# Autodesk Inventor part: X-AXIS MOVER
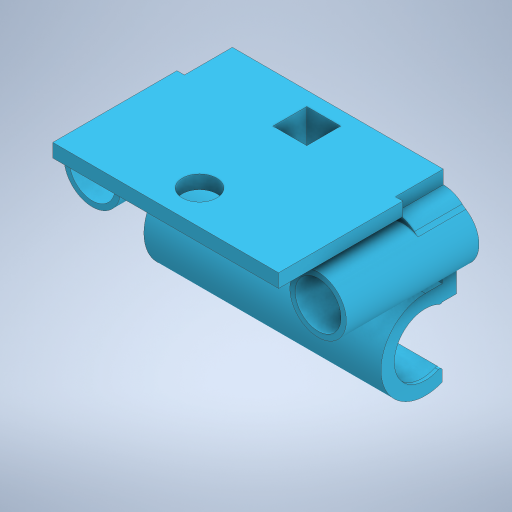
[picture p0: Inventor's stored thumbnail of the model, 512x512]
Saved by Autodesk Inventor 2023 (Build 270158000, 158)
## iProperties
Created: 2025-07
Part Number: X-AXIS MOVER
Material: Generic
Document SubType Name: Modeling
Designer: erjon
Density: 1 g/cm^3
Appearance: Default
Author: erjon
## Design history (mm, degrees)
feature "Base1"
sketch "Sketch1"
  geometry: L1 (-7, 2)-(-7, -1.767); L2 (-10, 9)-(0, 9); L3 (0, 0)-(0, 10.101) reference; L4 (-10, 9)-(0, 9); L5 (0, 10.101)-(-10, 10.101) reference; L6 (-10, 9.148)-(-10, 10.101) reference; L7 (-4, 9.148)-(-10, 9.148) reference; L8 (-4, 9)-(-4, 9.148) reference; L9 (-10, 9)-(-4, 9) reference; L10 (-10, 8)-(-10, 9) reference; L11 (-9.399, 7.335)-(-9.5, 7.5) reference; L12 (-9.308, -3.538)-(-9.241, -3.404) reference; L13 (-5, -5)-(-9, -5) reference; L14 (0, 10.101)-(0, 0) reference; L15 (-4.601, 7.335)-(-4.5, 7.5); L16 (-4, 8)-(-4, 9); L17 (-4.692, -3.538)-(-4.759, -3.404); L18 (-9, -5)-(-5, -5); L19 (-14, 0)-(-14, 10.101); L20 (-14, 10.101)-(-14, 0); L21 (-4, 9)-(-14, 9); L22 (-4, 9)-(-4, 9.148) reference; L23 (-4, 9)-(-14, 9); A1 r 5.85 centre (-7, 2) between (-9.241, -3.404) and (-9.399, 7.335) reference; A2 r 0.5 centre (-9.5, 8) between (-10, 8) and (-9.5, 7.5) reference; A3 r 5.85 centre (-7, 2) between (-9.241, -3.404) and (-9.399, 7.335) reference; A4 r 0.5 centre (-9.5, -4) between (-9.308, -3.538) and (-10, -4) reference; A5 r 1 centre (-9, -4) between (-10, -4) and (-9, -5) reference; A6 r 5 centre (-5, 0) between (-5, -5) and (0, 0) reference; A7 r 5.85 centre (-7, 2) between (-4.601, 7.335) and (-4.759, -3.404); A8 r 0.5 centre (-4.5, 8) between (-4.5, 7.5) and (-4, 8); A9 r 5.85 centre (-7, 2) between (-4.601, 7.335) and (-4.759, -3.404); A10 r 0.5 centre (-4.5, -4) between (-4, -4) and (-4.692, -3.538); A11 r 1 centre (-5, -4) between (-5, -5) and (-4, -4); A12 r 5 centre (-9, 0) between (-14, 0) and (-9, -5); 12 further points
  constraints: 22 end point, 21 symmetric about line, 12 point on circle, 6 centre point, 2 collinear, 2 point on line, 1 horizontal, 1 vertical, 6 other
  node "Projected Loop1"
extrude "Extrusion1" join sketch "Sketch1" stored distance "d0" = 10; taper "d1" = 0 deg
sketch "Sketch2"
  geometry: 1 further point
extrude "Extrusion2" cut sketch "Sketch1" distance "d2" = 100; taper "d3" = 0 deg
sketch "Sketch3"
  geometry: L1 (9.399, 7.335)-(14, 7.335); L2 (14, 7.335)-(14, 9); L3 (14, 9)-(10, 9); L4 (9.399, 7.335)-(9.5, 7.5) reference; L5 (10, 8)-(10, 9) reference; A1 r 0.5 centre (9.5, 8) between (9.5, 7.5) and (10, 8) reference; 1 further point
  constraints: 6 end point, 2 perpendicular, 1 horizontal
extrude "Extrusion3" join sketch "Sketch3" stored distance "d4" = 100; taper "d5" = 0 deg
sketch "Sketch4"
  geometry: L1 (39.682, -15.065)-(39.682, -12.299) reference; L2 (37.364, -1.4)-(37.364, 0) reference; L3 (0, 0)-(37.364, 0) reference; L4 (0, -1.4)-(0, 0) reference; L5 (-2.318, -12.299)-(-2.318, -15.065) reference; L6 (-2.318, -15.065)-(39.682, -15.065) reference; A1 r 5 centre (38.682, -7.4) between (39.682, -12.299) and (41.364, -3.18) reference; A2 r 5 centre (44.047, 1.039) between (40.705, -2.68) and (41.364, -3.18) reference; A3 r 5 centre (37.364, -6.4) between (40.705, -2.68) and (37.364, -1.4) reference; A4 r 5 centre (0, -6.4) between (0, -1.4) and (-3.341, -2.68) reference; A5 r 5 centre (-6.683, 1.039) between (-4, -3.18) and (-3.341, -2.68) reference; A6 r 5 centre (-1.318, -7.4) between (-4, -3.18) and (-2.318, -12.299) reference; 1 further point
extrude "Extrusion4" cut sketch "Sketch4" distance "d6" = 1.5; taper "d7" = 0 deg
sketch "Sketch5"
  geometry: L1 (33.682, -6)-(3.682, -6); L2 (18.682, -6)-(18.682, -12); L3 (39.682, -12)-(-2.318, -12) reference; L4 (18.682, -12)-(15.682, -12); L5 (15.682, -12)-(21.682, -12); L6 (21.682, -12)-(21.682, 0); L7 (37.364, 0)-(0, 0) reference; L8 (21.682, 0)-(15.682, 0); L9 (15.682, 0)-(15.682, -12); A1 r 5 centre (-1.318, -6) between (-2.318, -10.899) and (-4, -1.78) reference; 5 further points
  constraints: 14 end point, 3 perpendicular, 2 midpoint, 2 point on line, 1 horizontal, 1 horizontal alignment, 1 point on circle, 1 other
  dimensions: "d8" = 3 distance of L2.end L4.end; "d9" = 6 distance of L4.end L5.end; "d10" = 6 distance of L6.end L8.end
extrude "Extrusion5" cut sketch "Sketch5" distance "d11" = 6; taper "d12" = 0 deg
sketch "Sketch6"
  geometry: L1 (17, -22)-(1.318, -22) reference; L2 (23, -22)-(17, -22); L3 (17, -28)-(23, -28) reference; L4 (17, -22)-(17, -28); L5 (17, -28)-(23, -28); L6 (23, -28)-(23, -22); 1 further point
  constraints: 8 end point, 2 perpendicular, 1 collinear, 1 horizontal
extrude "Extrusion6" cut sketch "Sketch6" distance "d13" = 6; taper "d14" = 0 deg
sketch "Sketch7"
  geometry: L1 (-6, 0)-(0, 0) reference; L2 (-6, 0)-(-6, -0.8); L3 (-6, -0.148)-(-6, 0) reference; L4 (-6, -0.8)-(4, -0.8); L5 (4, -0.148)-(4, -9.148) reference; L6 (4, -0.8)-(4, 0); L7 (4, 0)-(-6, 0); L8 (4, -0.148)-(-6, -0.148) reference; 1 further point
  constraints: 8 end point, 1 collinear, 1 parallel, 1 perpendicular, 1 point on line, 1 vertical
  dimensions: "d15" = 0.8 distance of L1.start L2.end
extrude "Extrusion7" cut sketch "Sketch7" distance "d16" = 100; taper "d17" = 0 deg
fillet "Fillet1" dims "d18" = 4
sketch "Sketch8"
  geometry: C1 r 4.05 at (0, 0) reference; C2 r 4.1 at (0, 0); C3 r 4.05 at (-40, 0) reference; C4 r 4.1 at (-40, 0); 1 further point
  constraints: 2 centre point, 2 coincident
  dimensions: "d19" = 8.2 diameter of C2; "d20" = 8.2 diameter of C4
extrude "Extrusion8" cut sketch "Sketch8" distance "d21" = 15; taper "d22" = 0 deg
sketch "Sketch9"
  geometry: L1 (-4, -4.8)-(-4, -9.148) reference; L2 (5, -14.148)-(1, -14.148) reference; L3 (5.308, -12.686)-(5.241, -12.552) reference; L4 (5.399, -1.813)-(8.5, -1.813) reference; L5 (8.5, -1.813)-(8.5, 0.953) reference; L6 (8.5, 0.953)-(0, 0.953) reference; L7 (0, 0)-(0, 0.953) reference; L8 (6, 0)-(0, 0) reference; L9 (6, -0.8)-(6, 0) reference; L10 (6, -0.8)-(0, -0.8) reference; L11 (6, -0.8)-(8.5, -0.8); A1 r 4 centre (0, -4.8) between (0, -0.8) and (-4, -4.8) reference; A2 r 5 centre (1, -9.148) between (-4, -9.148) and (1, -14.148) reference; A3 r 1 centre (5, -13.148) between (5, -14.148) and (6, -13.148) reference; A4 r 0.5 centre (5.5, -13.148) between (6, -13.148) and (5.308, -12.686) reference; A5 r 5.85 centre (3, -7.148) between (5.399, -1.813) and (5.241, -12.552) reference; 1 further point
  constraints: 2 end point, 1 perpendicular, 1 point on line
extrude "Extrusion9" cut sketch "Sketch9" distance "d23" = 100; taper "d24" = 0 deg
sketch "Sketch10"
  geometry: L1 (6, -0.8)-(8.5, -0.8) reference; L2 (8.5, -0.8)-(8.5, -0.9); L3 (0, 0)-(0, 0.953) reference; L4 (6, -0.8)-(6, 0) reference; L5 (6, -0.8)-(6, -0.9); L6 (6, -0.9)-(8.5, -0.9); L7 (6, -0.9)-(0, -0.9); L8 (0, -0.9)-(0, -2.9); L9 (0, -2.9)-(8.5, -2.9); L10 (8.5, -0.8)-(8.5, 0.953) reference; L11 (8.5, -2.9)-(8.5, -0.9); L12 (8.5, -2.9)-(8.5, -8.75); L13 (8.5, -8.75)-(3, -8.75); L14 (6, -0.9)-(6, -16.004); L15 (6, -3.728)-(8.5, -3.728); 5 further points
  constraints: 22 end point, 7 perpendicular, 3 vertical, 2 coincident, 2 horizontal, 2 point on line, 6 other
  dimensions: "d25" = 0.1 distance of L1.end L2.end; "d26" = 2 distance of L7.end L8.end; "d27" = 5.85 distance of L9.end L12.end; "d28" = 5.5 distance of L12.end L13.end
extrude "Extrusion10" join sketch "Sketch10" stored distance "d29" = 100; taper "d30" = 0 deg
sketch "Sketch11"
  geometry: L1 (-6, -0.9)-(-6, 0) reference; L2 (-6, 0)-(0, 0) reference; L3 (0, 0)-(0, 0.953) reference; L4 (0, 0.953)-(-8.5, 0.953) reference; L5 (-8.5, -3.728)-(-8.5, 0.953) reference; L6 (-6, -3.728)-(-8.5, -3.728) reference; L7 (-6, -16.004)-(-6, -13.772) reference; L8 (-6, -0.9)-(-3, -0.9) reference; L9 (-6, -0.9)-(-6, -0.9); L10 (-6, -0.9)-(-6, -13.772); C1 r 5.5 at (-3, -8.75); A1 r 5.85 centre (-3, -8.75) between (-6, -13.772) and (-6, -3.728) reference; A2 r 7.85 centre (-3, -8.75) between (-6, -16.004) and (-3, -0.9) reference; 4 further points
  constraints: 4 end point, 2 vertical, 1 centre point, 1 coincident
  dimensions: "d31" = 11 diameter of C1
extrude "Extrusion11" join sketch "Sketch11" distance "d32" = 0.6; taper "d33" = 0 deg
fillet "Fillet2" dims "d34" = 0.5
sketch "Sketch12"
  geometry: C1 r 5.5 at (3, -8.75); A1 r 5.5 centre (3, -8.75) between (5.432, -3.817) and (5.292, -13.75) reference; A2 r 5.85 centre (3, -8.75) between (5.857, -13.855) and (6, -3.728); A3 r 0.5 centre (5.5, -14.204) between (5.857, -13.855) and (5.292, -13.75) reference; A4 r 0.5 centre (5.653, -3.368) between (5.432, -3.817) and (6, -3.728) reference; 1 further point
  constraints: 2 centre point, 2 coincident
extrude "Extrusion12" join sketch "Sketch12" distance "d35" = 0.6; taper "d36" = 0 deg
sketch "Sketch13"
  geometry: L1 (23, 28)-(23, 22) reference; L2 (23, 22)-(17, 22) reference; L3 (17, 22)-(17, 28) reference; L4 (17, 28)-(23, 28) reference; L5 (38.682, 30.5)-(1.318, 30.5) reference; L6 (1.318, 30.5)-(1.318, 22) reference; L7 (1.318, 22)-(0, 22) reference; L8 (0, 22)-(0, 0) reference; L9 (0, 0)-(40, 0) reference; L10 (40, 0)-(40, 22) reference; L11 (40, 22)-(38.682, 22) reference; L12 (38.682, 22)-(38.682, 30.5) reference; C1 r 3.05 at (20, 6) reference; 1 further point
extrude "Extrusion13" join sketch "Sketch13" distance "d37" = 1; taper "d38" = 0 deg
body "Solid1"
node "Projected Loop2"
node "Projected Loop3"
node "Projected Loop4"
node "Projected Loop5"
